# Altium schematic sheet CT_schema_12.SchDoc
size 389 x 385 mm
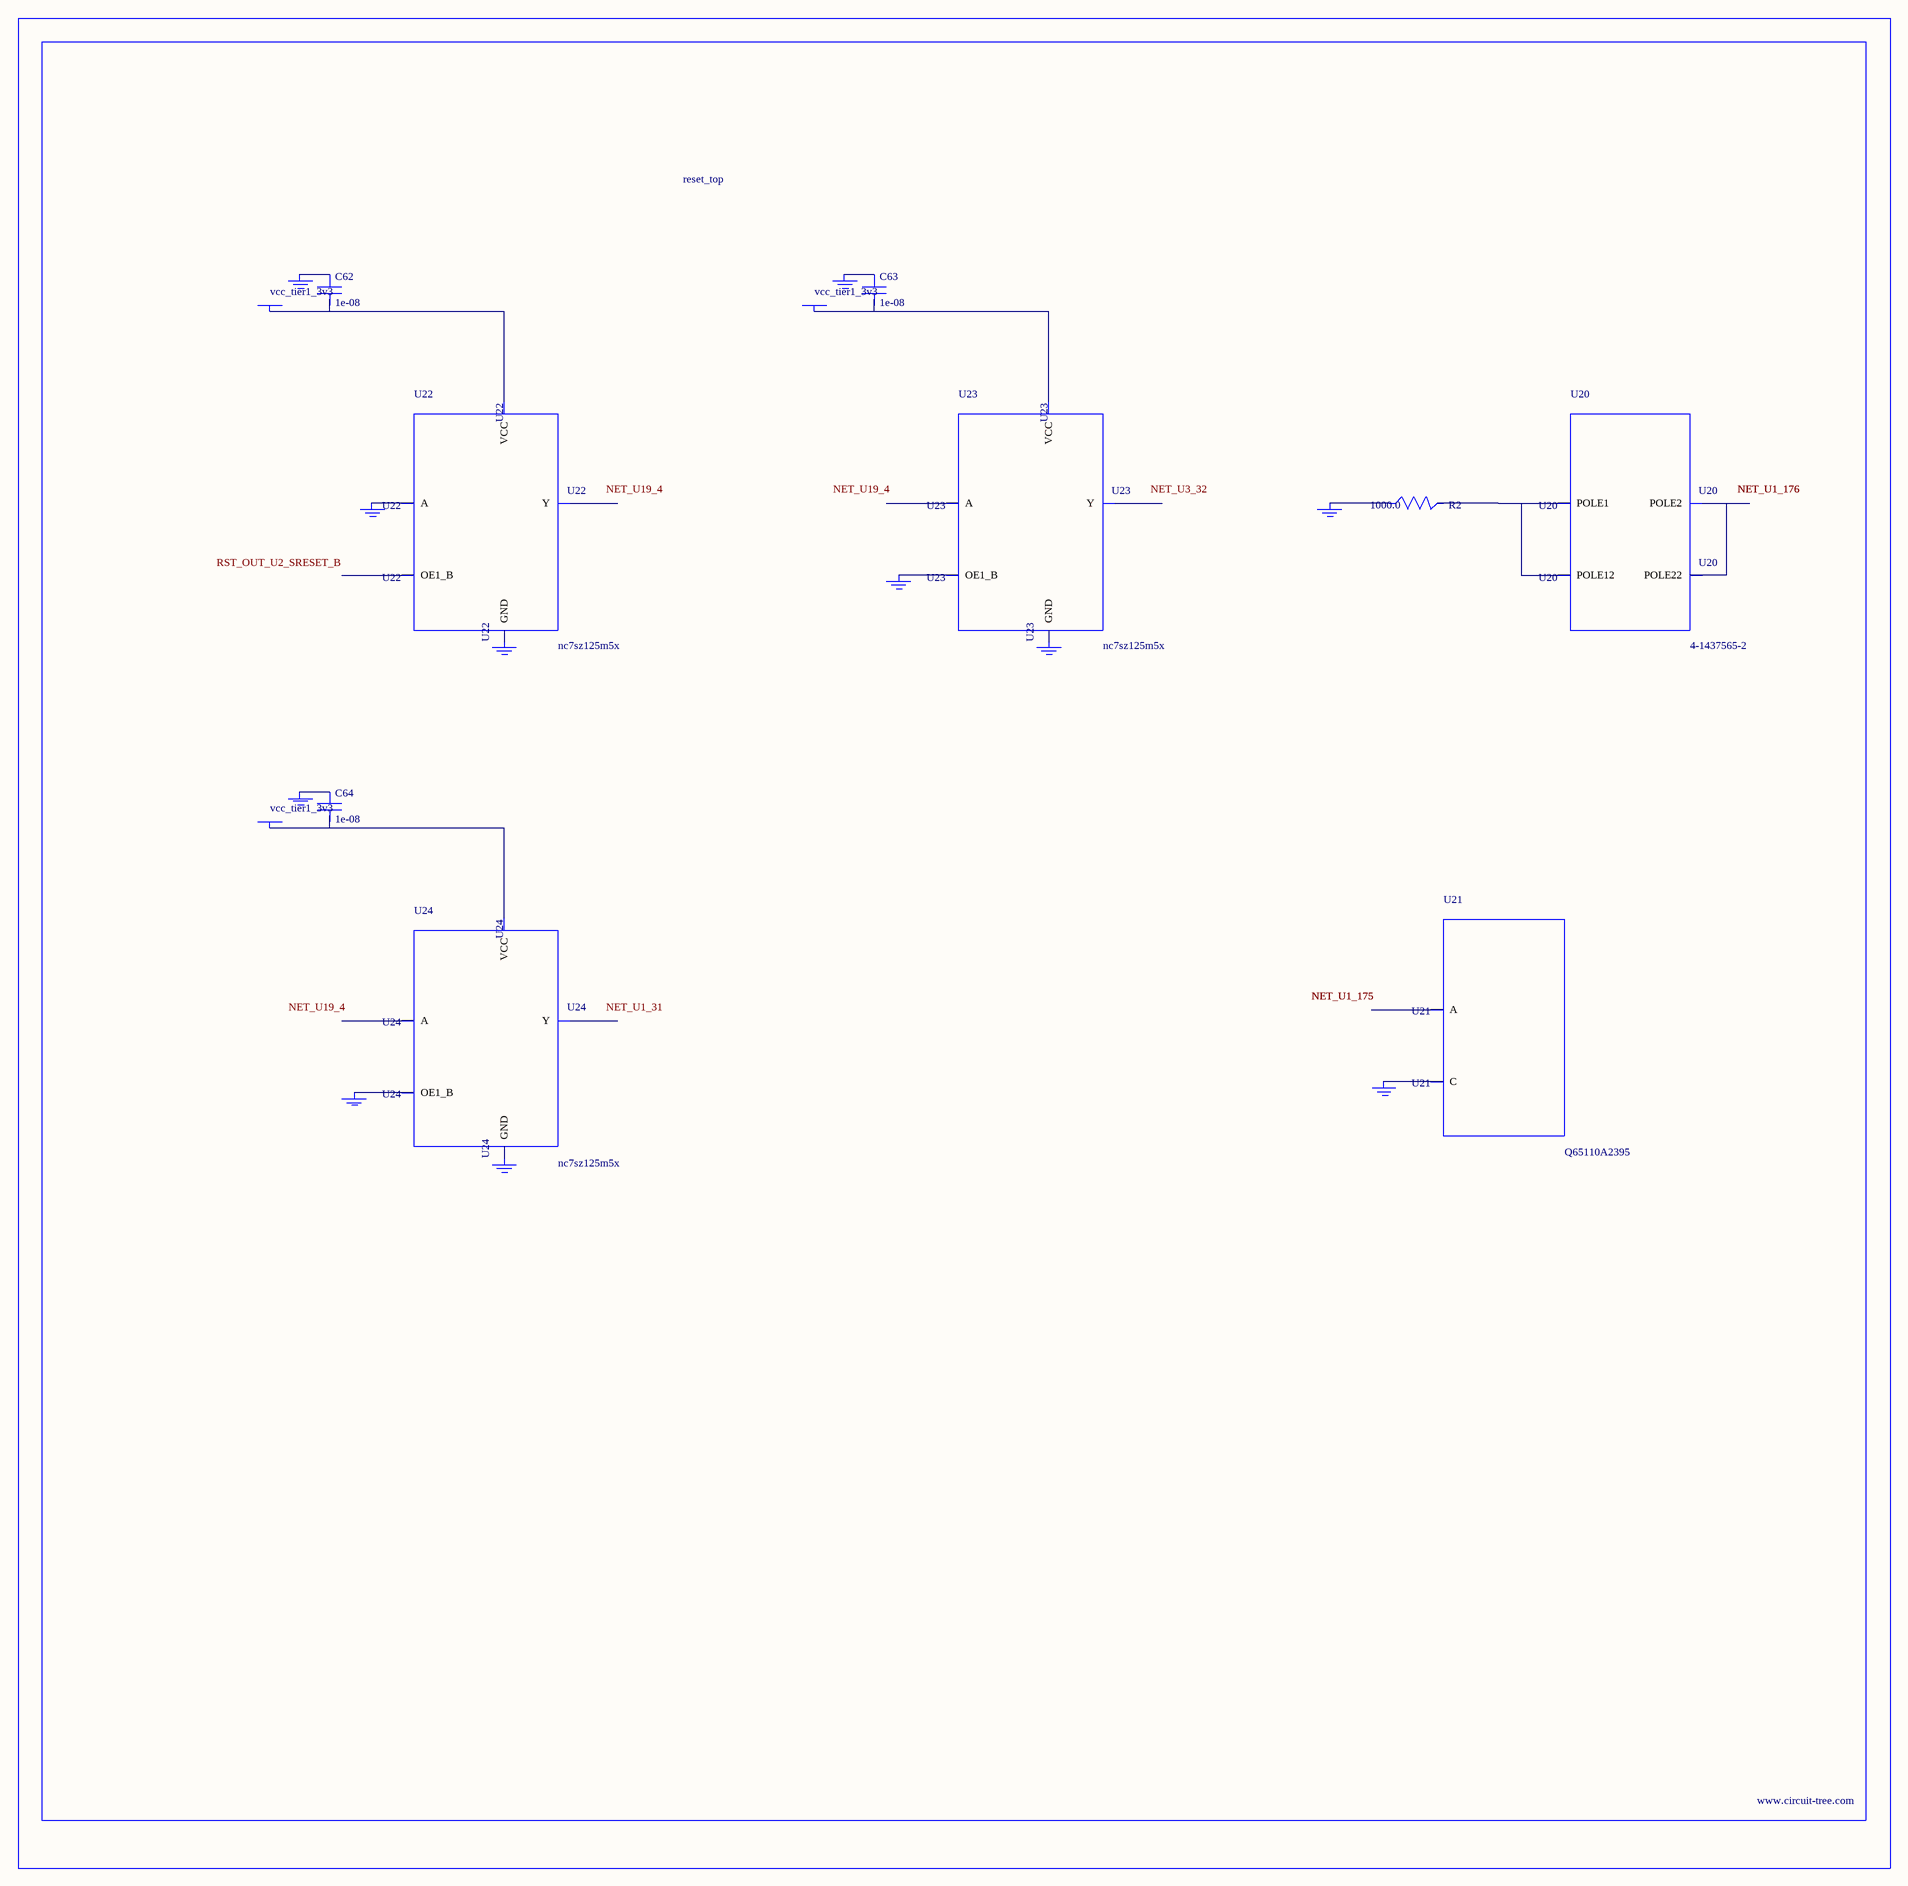
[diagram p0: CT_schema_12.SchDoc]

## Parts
BORDER11  (no value)
C62  1e-08  [C0402]
C63  1e-08  [C0402]
C64  1e-08  [C0402]
GND_INSTANCE_11_0  (no value)
GND_INSTANCE_11_1  (no value)
GND_INSTANCE_11_2  (no value)
GND_INSTANCE_11_3  (no value)
GND_INSTANCE_11_4  (no value)
GND_INSTANCE_11_5  (no value)
GND_INSTANCE_11_6  (no value)
GND_INSTANCE_11_7  (no value)
GND_INSTANCE_11_8  (no value)
GND_INSTANCE_11_9  (no value)
GND_INSTANCE_11_10  (no value)
POWER_INSTANCE_11_0  vcc_tier1_3v3
POWER_INSTANCE_11_1  vcc_tier1_3v3
POWER_INSTANCE_11_2  vcc_tier1_3v3
R2  1000.0  [R0603]
U20  4-1437565-2  [SW_4-1437565-2]
U21  Q65110A2395  [LGM67K-G1J2-24-Z]
U22  nc7sz125m5x  [NC7SZ125M5X]
U23  nc7sz125m5x  [NC7SZ125M5X]
U24  nc7sz125m5x  [NC7SZ125M5X]

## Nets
NetC62_1: C62.1 GND_INSTANCE_11_2.0(GND)
NetC62_2: C62.2 POWER_INSTANCE_11_0.0(PWR) U22.5(VCC)
NetC63_1: C63.1 GND_INSTANCE_11_5.0(GND)
NetC63_2: C63.2 POWER_INSTANCE_11_1.0(PWR) U23.5(VCC)
NetC64_1: C64.1 GND_INSTANCE_11_8.0(GND)
NetC64_2: C64.2 POWER_INSTANCE_11_2.0(PWR) U24.5(VCC)
NetGND_INSTANCE_11_0_0: GND_INSTANCE_11_0.0(GND) R2.1
NetGND_INSTANCE_11_1_0: GND_INSTANCE_11_1.0(GND) U21.C
NetGND_INSTANCE_11_3_0: GND_INSTANCE_11_3.0(GND) U22.2(A)
NetGND_INSTANCE_11_4_0: GND_INSTANCE_11_4.0(GND) U22.3(GND)
NetGND_INSTANCE_11_6_0: GND_INSTANCE_11_6.0(GND) U23.1(OE1_B)
NetGND_INSTANCE_11_7_0: GND_INSTANCE_11_7.0(GND) U23.3(GND)
NetGND_INSTANCE_11_9_0: GND_INSTANCE_11_9.0(GND) U24.1(OE1_B)
NetGND_INSTANCE_11_10_0: GND_INSTANCE_11_10.0(GND) U24.3(GND)
NetR2_2: R2.2 U20.1(POLE1) U20.2(POLE12)
NetU20_3: U20.3(POLE2) U20.4(POLE22)

Not connected (* = marked no-connect by the designer): U21 A; U22 1(OE1_B) 4(Y); U23 2(A) 4(Y); U24 2(A) 4(Y)

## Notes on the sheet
- Labels drawn without touching a wire or pin: NET_U1_31, NET_U3_32, NET_U19_4, RST_OUT_U2_SRESET_B

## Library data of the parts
BORDER11 = BORDER_PAGE11
C62-C64 = C0402C103K3RAC
GND_INSTANCE_11_0-GND_INSTANCE_11_10 = GND
POWER_INSTANCE_11_0-POWER_INSTANCE_11_2 = PWR
R2 = RC0603JR-071KL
